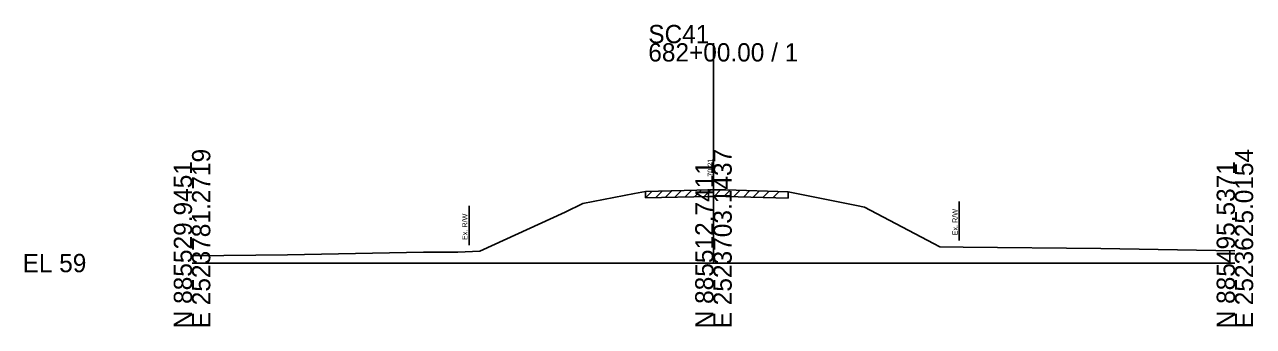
# Model space of a CAD drawing. Extents: x -26 to 183, y -10 to 24021.
# Drawn here: x -25.7 to 162.8, y 12990.3 to 13036.5 of the extents above; entities that cross this region are included whole.
import ezdxf

# ---------------------------------------------------------------- set-up
doc = ezdxf.new("R2010")
doc.units = 0
for name, color, linetype in [('RD_GPK_XS_Cell', 7, 'Continuous'), ('RD_XS_ExGround', 7, 'Continuous'), ('RD_XS_ExPaveRet', 7, 'Continuous'), ('RD_XS_ExRW', 7, 'Continuous'), ('RD_XS_TX_Elev_EX', 7, 'Continuous')]:
    doc.layers.add(name, color=color, linetype=linetype)

msp = doc.modelspace()

# ---------------------------------------------------------------- linework, layer by layer
at = {"layer": 'RD_GPK_XS_Cell'}
for p, q in [((80, 13000), (80, 13033.66)), ((0, 13000), (80, 13000)), ((80, 13000), (160, 13000))]:
    msp.add_line(p, q, dxfattribs=at)
at = {"layer": 'RD_XS_ExGround'}
for p, q in [((59.98, 13009.12), (67.89, 13010.64)), ((67.89, 13010.64), (69.59, 13010.98)), ((69.59, 13010.98), (79.42, 13011.19)), ((79.42, 13011.19), (80, 13011.21)), ((80, 13011.21), (80.67, 13011.22)), ((80.67, 13011.22), (81.9, 13011.19)), ((81.9, 13011.19), (91.46, 13010.93)), ((91.46, 13010.93), (101.93, 13008.83)), ((57.27, 13007.81), (59.98, 13009.12)), ((101.93, 13008.83), (103.15, 13008.56)), ((44.13, 13001.81), (57.27, 13007.81)), ((103.15, 13008.56), (113.76, 13002.98)), ((0, 13001.11), (14.67, 13001.28)), ((14.67, 13001.28), (35.53, 13001.66)), ((35.53, 13001.66), (40.8, 13001.65)), ((40.8, 13001.65), (44.13, 13001.81)), ((113.76, 13002.98), (114.71, 13002.48)), ((114.71, 13002.48), (118.33, 13002.44)), ((118.33, 13002.44), (139.45, 13002.23)), ((139.45, 13002.23), (160, 13001.87))]:
    msp.add_line(p, q, dxfattribs=at)
at = {"layer": 'RD_XS_ExPaveRet'}
for p, q in [((69.59, 13009.98), (70.61, 13011)), ((69.59, 13009.98), (69.59, 13010.98)), ((71.09, 13010.01), (72.11, 13011.03)), ((72.59, 13010.04), (73.61, 13011.07)), ((74.09, 13010.08), (75.11, 13011.1)), ((75.59, 13010.11), (76.61, 13011.13)), ((77.09, 13010.14), (78.11, 13011.17)), ((78.59, 13010.18), (79.61, 13011.2)), ((80.09, 13010.21), (81.09, 13011.21)), ((81.59, 13010.19), (82.56, 13011.17)), ((83.09, 13010.15), (84.06, 13011.13)), ((84.59, 13010.11), (85.56, 13011.09)), ((86.09, 13010.07), (87.06, 13011.05)), ((87.59, 13010.03), (88.56, 13011.01)), ((89.09, 13009.99), (90.06, 13010.97)), ((91.46, 13010.93), (91.46, 13009.93)), ((69.59, 13009.98), (79.42, 13010.19)), ((79.42, 13010.19), (80, 13010.21)), ((80, 13010.21), (80.67, 13010.22)), ((80.67, 13010.22), (81.9, 13010.19)), ((81.9, 13010.19), (91.46, 13009.93))]:
    msp.add_line(p, q, dxfattribs=at)
at = {"layer": 'RD_XS_ExRW'}
for p, q in [((117.71, 13009.45), (117.71, 13003.45)), ((42.5, 13008.74), (42.5, 13002.74))]:
    msp.add_line(p, q, dxfattribs=at)

# ---------------------------------------------------------------- texts
at = {"layer": 'RD_GPK_XS_Cell'}
for s, p in [('SC41', (70, 13033.66)), ('682+00.00 / 1', (70, 13030.86)), ('EL 59', (-26, 12998.6))]:
    msp.add_text(s, height=2.8, dxfattribs=at).set_placement(p)
for s, p in [('E 2523781.2719', (2.8, 12990)), ('E 2523703.1437', (82.8, 12990)), ('E 2523625.0154', (162.8, 12990)), ('N 885529.9451', (0, 12990)), ('N 885512.7411', (80, 12990)), ('N 885495.5371', (160, 12990))]:
    msp.add_text(s, height=2.8, rotation=90, dxfattribs=at).set_placement(p)
at = {"layer": 'RD_XS_ExRW'}
for p in [(42.25, 13003.52), (117.46, 13004.24)]:
    msp.add_text('Ex. R/W ', height=0.8, rotation=90, dxfattribs=at).set_placement(p)
at = {"layer": 'RD_XS_TX_Elev_EX'}
msp.add_text('70.21', height=0.8, rotation=90, dxfattribs=at).set_placement((79.9, 13013.21))

doc.saveas('drawing.dxf')
